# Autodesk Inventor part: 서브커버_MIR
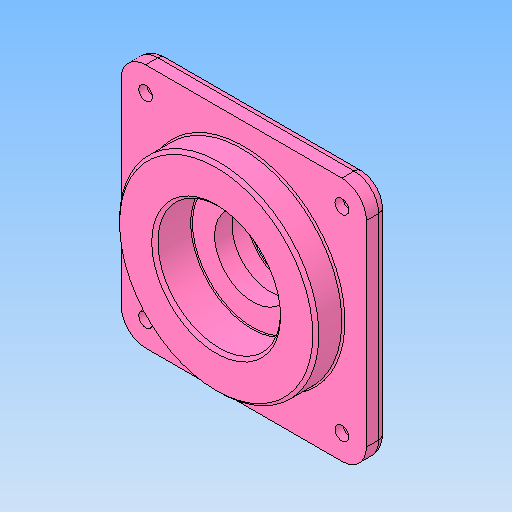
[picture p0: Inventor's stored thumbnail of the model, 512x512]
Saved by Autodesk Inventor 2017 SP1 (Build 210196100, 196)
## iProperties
Created: 2018-09
Part Number: 서브커버_MIR
Material: 알루미늄 6061
Document SubType Name: Modeling
Designer: MRC
Mass: 206.54 g
Surface Area: 196.569 cm^2
Volume: 76.2142 cm^3
Density: 2.71 g/cm^3
Appearance: 알루미늄 - 평지
Author: mduedu
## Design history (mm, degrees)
derived "서브커버.ipt"
  sketch "스케치1"
    geometry: L1 (40, -40)-(-40, -40) reference; L2 (-40, -40)-(-40, 40) reference; L3 (-40, 40)-(40, 40) reference; L4 (40, 40)-(40, -40) reference; L5 (40, -40)-(-40, 40) reference; L6 (-40, -40)-(40, 40) reference; 1 further point
  sketch "스케치2"
    geometry: C1 r 30 at (0, 0) reference; 1 further point
  sketch "스케치3"
    geometry: C1 r 32.5 at (0, 0) reference; 1 further point
  sketch "스케치4"
    geometry: L1 (32.5, -9)-(-32.5, -9) reference; L2 (-30, 17)-(30, 17) reference; L3 (0, 17)-(0, -9) reference; L4 (0, -9)-(-20, -9) reference; L5 (-20, -9)-(-20, 3) reference; L6 (-20, 3)-(0, 3) reference; L7 (0, 3)-(0, -9) reference; L8 (0, 3)-(-12.5, 3) reference; L9 (-12.5, 3)-(-12.5, 8.7) reference; L10 (-12.5, 8.7)-(0, 8.7) reference; L11 (0, 8.7)-(0, 3) reference; L12 (0, 8.7)-(-16, 8.7) reference; L13 (-16, 8.7)-(-16, 17) reference; L14 (-16, 17)-(0, 17) reference; L15 (0, 17)-(0, 8.7) reference; 1 further point
  sketch "스케치5"
    geometry: A1 r 8 centre (32, 32) between (40, 32) and (32, 40) reference; A2 r 8 centre (32, -32) between (32, -40) and (40, -32) reference; A3 r 8 centre (-32, -32) between (-40, -32) and (-32, -40) reference; A4 r 8 centre (-32, 32) between (-32, 40) and (-40, 32) reference; 5 further points
feature "솔리드1::서브커버.ipt"
tag "피쳐 태그1"
node "솔리드1"
